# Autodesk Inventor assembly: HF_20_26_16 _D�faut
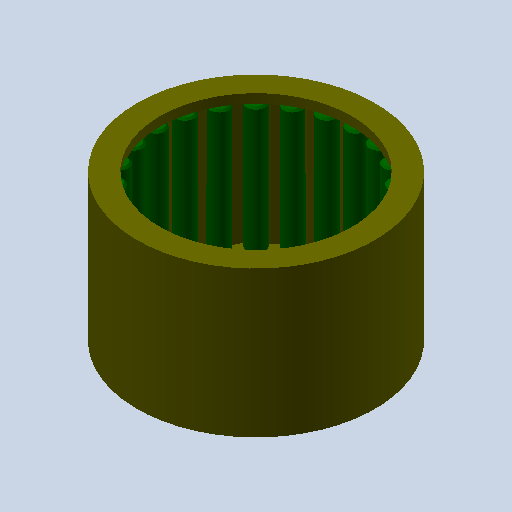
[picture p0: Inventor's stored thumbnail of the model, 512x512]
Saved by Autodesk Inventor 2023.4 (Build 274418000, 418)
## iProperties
Created: 2011-01
Part Number: HF_20_26_16 _D�faut
Document SubType Name: Assembly
Designer: eric
Mass: 2.78295 g
Surface Area: 53.1486 cm^2
Volume: 2.78295 cm^3
Density: 1 g/cm^3
Author: eric
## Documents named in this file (3)
- C:\Users\bruno\Documents\1-Cours-2024-25\TSsI\7-Dynamique\chariot de golf\chariot_de_golf\chariot_de_golf_trolem\HF_20_26_16 _Defaut.iam
- C:\Users\bruno\Documents\1-Cours-2024-25\TSsI\7-Dynamique\chariot de golf\chariot_de_golf\chariot_de_golf_trolem\aiguilles_HF20_26_16_Defaut.ipt
- C:\Users\bruno\Documents\1-Cours-2024-25\TSsI\7-Dynamique\chariot de golf\chariot_de_golf\chariot_de_golf_trolem\cage_HF20_26_16_Defaut.ipt
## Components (25 placed, 2 different names)
1. aiguilles_HF20_26_16_Defaut:1
2. aiguilles_HF20_26_16_Defaut:2
3. aiguilles_HF20_26_16_Defaut:3
4. aiguilles_HF20_26_16_Defaut:4
5. aiguilles_HF20_26_16_Defaut:5
6. cage_HF20_26_16_Defaut:1
7. aiguilles_HF20_26_16_Defaut:6
8. aiguilles_HF20_26_16_Defaut:7
9. aiguilles_HF20_26_16_Defaut:8
10. aiguilles_HF20_26_16_Defaut:9
11. aiguilles_HF20_26_16_Defaut:10
12. aiguilles_HF20_26_16_Defaut:11
13. aiguilles_HF20_26_16_Defaut:12
14. aiguilles_HF20_26_16_Defaut:13
15. aiguilles_HF20_26_16_Defaut:14
16. aiguilles_HF20_26_16_Defaut:15
17. aiguilles_HF20_26_16_Defaut:16
18. aiguilles_HF20_26_16_Defaut:17
19. aiguilles_HF20_26_16_Defaut:18
20. aiguilles_HF20_26_16_Defaut:19
21. aiguilles_HF20_26_16_Defaut:20
22. aiguilles_HF20_26_16_Defaut:21
23. aiguilles_HF20_26_16_Defaut:22
24. aiguilles_HF20_26_16_Defaut:23
25. aiguilles_HF20_26_16_Defaut:24
